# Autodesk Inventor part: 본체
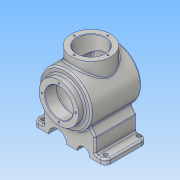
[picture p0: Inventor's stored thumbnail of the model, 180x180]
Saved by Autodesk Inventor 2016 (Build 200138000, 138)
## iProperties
Created: 2018-08
Part Number: 본체
Material: 알루미늄 6061
Document SubType Name: Modeling
Designer: Administrator
Density: 2.7 g/cm^3
Appearance: 알루미늄 - 평지
Mass: 1879.09 g
Surface Area: 1087.47 cm^2
Volume: 695.959 cm^3
Author: Administrator
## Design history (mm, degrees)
sketch "스케치1"
  geometry: L1 (-62, 82)-(135.009, 82); L2 (-62, 82)-(-62, 120); L3 (-62, 120)-(-50, 120); L4 (-50, 120)-(-50, 132); L5 (-50, 132)-(46.671, 132); L6 (46.671, 132)-(46.671, 82); A1 r 116 centre (-58, 82) between (58, 82) and (46.671, 132); 1 further point
  constraints: 12 end point, 4 perpendicular, 3 point on line, 2 point on circle, 1 centre point, 1 horizontal, 1 vertical
  dimensions: "d0" = 82 distance from line of point (0, 0) L1; "d1" = 76 diameter of L3 L1; "d2" = 100 diameter of L5 L1; "d6" = 12 distance between parallel lines of L2 L4; "d7" = 108 distance from line of L4 A1.start; "d8" = 116 radius of A1; "d172" = 50 distance from line of point (0, 0) L4
revolve "회전1" sketch "스케치1" stored, may be unused: angle "d9" = 90 deg
node "작업 평면1"
sketch "스케치2"
  geometry: C1 r 38 at (0, 0); 1 further point
  constraints: 1 centre point, 1 coincident
  dimensions: "d11" = 76 diameter of C1
extrude "돌출1" join sketch "스케치2" stored distance "d12" = 10; taper "d13" = 0 deg
node "작업 평면2"
sketch "스케치10"
  geometry: C1 r 48.248 at (0, 0) reference; C2 r 32.5 at (0, 0); 1 further point
  constraints: 1 centre point, 1 coincident, 1 other
  dimensions: "d82" = 65 diameter of C2
feature "엠보싱1" sketch "스케치10" dims "d0" = 82, "d83" = 0.5, "d84" = 0
sketch "스케치12"
  geometry: 1 further point
sketch "스케치14"
  geometry: 1 further point
sketch "스케치15"
  geometry: 1 further point
node "작업 평면5"
sketch "스케치16"
  geometry: L1 (0, 27.97)-(0, -82); L2 (0, -82)-(70, -82); L3 (70, -82)-(70, -72); L4 (70, -72)-(50, -72); L5 (50, -72)-(50, -43.437); L6 (70, -72)-(50, -43.437); L7 (50, -43.437)-(0, 27.97); C1 r 50 at (0, 0) reference
  constraints: 14 end point, 4 perpendicular, 1 vertical
  dimensions: "d102" = 10 distance between parallel lines of L2 L4; "d103" = 20 distance between parallel lines of L5 L3; "d105" = 70 distance between parallel lines of L1 L3; "d108" = 35 deg angle of L3 L6; "d109" = 35 deg angle of L3 L7
extrude "돌출7" join sketch "스케치16" distance "d110" = 80; taper "d111" = 0 deg
sketch "스케치17"
  geometry: L1 (-62, 44)-(-62, 120) reference; L2 (-62, 82)-(58, 82); L3 (-62, 82)-(-62, 109); L4 (-62, 109)-(-40, 109); L5 (-40, 109)-(-40, 122); L6 (-40, 122)-(40.163, 122); L7 (-62, 82)-(48, 82); A1 r 116 centre (-58, 82) between (46.671, 32) and (46.671, 132) reference; A2 r 106 centre (-58, 82) between (48, 82) and (40.163, 122); 2 further points
  constraints: 12 end point, 3 perpendicular, 3 point on circle, 2 point on line, 1 centre point, 1 horizontal, 1 midpoint
  dimensions: "d116" = 10 radial gap between concentric circles of A1 A2; "d117" = 54 diameter of L4 L2; "d118" = 80 diameter of L6 L2; "d119" = 22 distance between parallel lines of L1 L5
revolve "회전3" sketch "스케치17" stored, may be unused: angle "d120" = 90 deg
sketch "스케치18"
  geometry: C1 r 38 at (0, 0) reference; C2 r 27 at (0, 0)
  constraints: 1 centre point, 1 coincident
  dimensions: "d121" = 54 diameter of C2
extrude "돌출8" cut sketch "스케치18" stored distance "d122" = 80; taper "d123" = 0 deg
fillet "모깎기6" dims "d124" = 10
sketch "스케치19"
  geometry: L1 (60, -82)-(-60, -82) reference; C1 r 12.5 at (27.5, -82); C2 r 17.5 at (-22.5, -82); 1 further point
  constraints: 2 centre point, 2 point on line
  dimensions: "d125" = 25 diameter of C1; "d126" = 27.5 distance of point (0, -82) C1.centre; "d127" = 35 diameter of C2; "d128" = 22.5 distance of point (0, -82) C2.centre
extrude "돌출9" cut sketch "스케치19" stored distance "d129" = 80; taper "d130" = 0 deg
sketch "스케치20" dims "d131" = 65
  geometry: C1 r 27 at (0, 0) reference; C2 r 38 at (0, 0) reference; 2 further points
  constraints: 2 vertical alignment, 1 coincident, 2 other
hole "구멍4" sketch "스케치20" at (0, 32.5) diameter "d132" = 3.242; stored, may be unused: countersink angle "d136" = 90 deg, drill point angle "d138" = 118 deg; dims "d133" = 8, "d134" = 4, "d135" = 2, "d137" = 10
sketch "스케치21" dims "d142" = 65
  geometry: C1 r 27 at (0, 0) reference; C2 r 38 at (0, 0) reference; 3 further points
  constraints: 2 vertical alignment, 1 coincident, 2 other
hole "구멍5" sketch "스케치21" at (0, 32.5) diameter "d143" = 3.242; stored, may be unused: countersink angle "d147" = 90 deg, drill point angle "d149" = 118 deg; dims "d144" = 8, "d145" = 4, "d146" = 2, "d148" = 10
hole "구멍6" diameter "d155" = 8; stored, may be unused: countersink angle "d159" = 90 deg, drill point angle "d161" = 118 deg; dims "d153" = 10, "d154" = 10, "d156" = 8, "d157" = 4, "d158" = 2, "d160" = 10
chamfer "모따기3" distance "d162" = 1; stored, may be unused: second distance "d163" = 2, angle "d164" = 45 deg
chamfer "모따기4" distance "d165" = 1; stored, may be unused: second distance "d166" = 2, angle "d167" = 45 deg
fillet "모깎기7" dims "d168" = 3
fillet "모깎기8" dims "d169" = 3
fillet "모깎기9" dims "d170" = 3
fillet "모깎기10" dims "d171" = 3
sketch "스케치22"
  geometry: L1 (-103.269, 189.123)-(120.167, 189.123); L2 (120.167, 189.123)-(120.167, -51.16); L3 (120.167, -51.16)-(-103.269, -51.16); L4 (-103.269, -51.16)-(-103.269, 189.123); 1 further point
  constraints: 8 end point, 2 parallel, 1 horizontal, 1 perpendicular
extrude "돌출10" cut sketch "스케치22" stored distance "d173" = 80; taper "d174" = 0 deg
node "솔리드1"
mirror "대칭5"
pattern_circular "원형 패턴3" dims angle "d140" = 360 deg
pattern_circular "원형 패턴4" dims angle "d151" = 360 deg
mirror "대칭6"
mirror "대칭7"
node "투영된 루프2"
other parameters: "d10" = 147, "d101" = -8
